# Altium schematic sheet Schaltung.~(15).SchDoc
size A4; PageSetup: Record=PageOptions|CenterHorizontal=True|CenterVertical=True|PrintScale=0.97|XCorrection=1.00|YCorrection=1.00|PrintKind=0|BorderSize=5000000|LeftOffset=0|BottomOffset=0|Orientation=2|PaperLength=1000|PaperWidth=1000|Scale=100|PaperSource=7|PrintQuality=-4|MediaType=1|DitherType=10|PaperKind=A4|PrintScaleMode=1
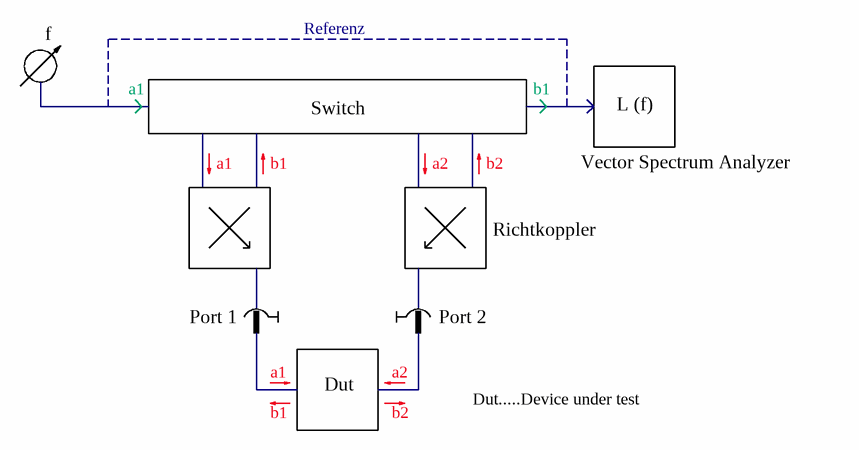
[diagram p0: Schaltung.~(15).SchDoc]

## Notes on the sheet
- f
- Referenz
- a1
- Switch
- b1
- L (f)
- a2
- b2
- Vector Spectrum Analyzer
- Richtkoppler
- Port 1
- Port 2
- Dut
- Dut.....Device under test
